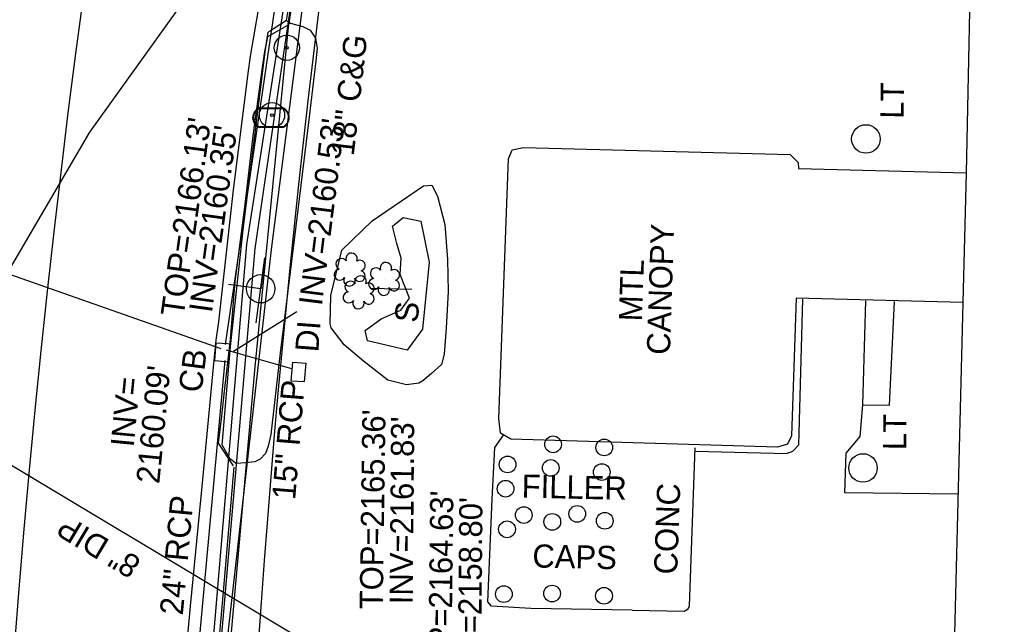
# Model space of a CAD drawing. Extents: x 945964 to 948456, y 631061 to 636061.
# Drawn here: x 946815.5 to 946985.2, y 633029 to 633133.3 of the extents above; entities that cross this region are included whole.
import ezdxf

# ---------------------------------------------------------------- set-up
doc = ezdxf.new("R2010")
doc.units = 0
for name, color, linetype in [('Exist Boundary County Line', 7, 'Continuous'), ('Exist Building', 7, 'Continuous'), ('Exist Building Metal Canopy', 7, 'Continuous'), ('Exist Building Metal Canopy Text', 7, 'Continuous'), ('Exist Horizontal Alignment', 7, 'Continuous'), ('Exist Other Culture Gas Pump or Vent CELL', 7, 'Continuous'), ('Exist Other Culture Gas Pump or Vent Text', 7, 'Continuous'), ('Exist Other Culture Sign CELL', 7, 'Continuous'), ('Exist Other Culture Sign Text', 7, 'Continuous'), ('Exist Right of Way Line', 7, 'Continuous'), ('Exist Roads Change in Surface', 7, 'Continuous'), ('Exist Roads Change in Surface Text', 7, 'Continuous'), ('Exist Roads Curbs', 7, 'Continuous'), ('Exist Roads Curbs Text', 7, 'Continuous'), ('Exist Roads EOP', 7, 'Continuous'), ('Exist Roads EOP Other', 7, 'Continuous'), ('Exist Structure Minor Catch Basin', 7, 'Continuous'), ('Exist Structure Minor Catch Basin Text', 7, 'Continuous'), ('Exist Structure Minor Catch Basin Top Elevation', 7, 'Continuous'), ('Exist Structure Minor Drop Inlet', 7, 'Continuous'), ('Exist Structure Minor Drop Inlet Text', 7, 'Continuous'), ('Exist Structure Minor Drop Inlet Top Elevation', 7, 'Continuous'), ('Exist Structure Minor Pipes RCP 15 Inch', 7, 'Continuous'), ('Exist Structure Minor Pipes RCP 15 Inch Invert', 7, 'Continuous'), ('Exist Structure Minor Pipes RCP 15 Inch Text', 7, 'Continuous'), ('Exist Structure Minor Pipes RCP 18 Inch', 7, 'Continuous'), ('Exist Structure Minor Pipes RCP 18 Inch Invert', 7, 'Continuous'), ('Exist Structure Minor Pipes RCP 24 Inch', 7, 'Continuous'), ('Exist Structure Minor Pipes RCP 24 Inch Invert', 7, 'Continuous'), ('Exist Structure Minor Pipes RCP 24 Inch Text', 7, 'Continuous'), ('Exist Utilities Gas UG Line SUE', 7, 'Continuous'), ('Exist Utilities Other Located Object CELL', 7, 'Continuous'), ('Exist Utilities Other Pole CELL', 7, 'Continuous'), ('Exist Utilities Other Pole With Base Text', 7, 'Continuous'), ('Exist Utilities Power Joint Use Telephone CELL', 7, 'Continuous'), ('Exist Utilities Sanitary Sewer Manhole Text', 7, 'Continuous'), ('Exist Utilities Sanitary Sewer UG Line', 7, 'Continuous'), ('Exist Utilities Sanitary Sewer UG Line Invert Elevation', 7, 'Continuous'), ('Exist Utilities Sanitary Sewer UG Line Text', 7, 'Continuous'), ('Exist Utilities Telephone UG Cable SUE', 7, 'Continuous'), ('Exist Utilities Telephone UG FO SUE', 7, 'Continuous'), ('Exist Utilities Water Meter CELL', 7, 'Continuous'), ('Exist Utilities Water UG Line SUE', 7, 'Continuous'), ('Exist Vegetation Hedge Row', 7, 'Continuous'), ('Exist Vegetation Shrub CELL', 7, 'Continuous')]:
    doc.layers.add(name, color=color, linetype=linetype)

# ---------------------------------------------------------------- blocks, each defined once
blk = doc.blocks.new('EXIST UTILITIES POWER JOINT USE TELEPHONE')
at = {"layer": 'Exist Utilities Power Joint Use Telephone CELL'}
blk.add_line((0, 0), (0, 0), dxfattribs=at)
blk.add_lwpolyline([(-0.1188, 0), (0.108, -0.0008), (0, -0.0004), (0, 0.1125)], dxfattribs=at)
blk.add_circle((0, 0.0001), 0.049, dxfattribs=at)
blk = doc.blocks.new('EXIST UTILITIES OTHER POLE')
at = {"layer": 'Exist Utilities Other Pole CELL'}
blk.add_circle((0, 0), 0.0493, dxfattribs=at)

msp = doc.modelspace()

# ---------------------------------------------------------------- linework, layer by layer
at = {"layer": 'Exist Boundary County Line'}
for p, q in [((947092.82, 633483.47), (946827.48, 633113.91)), ((946827.48, 633113.91), (946750.1, 632981.71))]:
    msp.add_line(p, q, dxfattribs=at)
at = {"layer": 'Exist Building'}
msp.add_lwpolyline([(946978.8, 633106.89), (946978.21, 633084.49), (946976.66, 633022.75), (947059.2, 633020.29), (947060.88, 633083.15), (947040.77, 633083.6), (947042.05, 633115.14), (947051.3, 633115.11), (947050.84, 633101.74), (947104.34, 633099.63), (947106.1, 633132.87), (947031.58, 633135.37), (947033.53, 633169.99), (946989.73, 633171.14), (946989.49, 633154.15), (946979.77, 633154.44)], close=True, dxfattribs=at)
at = {"layer": 'Exist Building Metal Canopy'}
msp.add_lwpolyline([(946978.21, 633084.49), (946949.46, 633085.25), (946948.64, 633061.53), (946947.97, 633060.09), (946946.23, 633059.56), (946900.24, 633060.93), (946898.42, 633061.98), (946898.13, 633064.51), (946899.81, 633109.29), (946900.43, 633110.84), (946902.43, 633111.27), (946948.43, 633110.06), (946949.8, 633108.68), (946949.89, 633107.64), (946978.8, 633106.89), (946978.21, 633084.49)], dxfattribs=at)
at = {"layer": 'Exist Horizontal Alignment'}
msp.add_arc((948718.82, 632879.65), 1909.86, 158.53343, 198.31343, dxfattribs=at)
at = {"layer": 'Exist Other Culture Gas Pump or Vent CELL'}
for centre in [(946907.51, 633060.05), (946916.35, 633059.51), (946899.66, 633056.58), (946907.1, 633055.98), (946915.92, 633055.27), (946899.32, 633052.4), (946911.69, 633048.05), (946902.46, 633047.85), (946907.38, 633046.68), (946916.44, 633046.86), (946899.56, 633045.39), (946899.02, 633034.22), (946907.33, 633034.31), (946916.3, 633033.93)]:
    msp.add_circle(centre, 1.44, dxfattribs=at)
at = {"layer": 'Exist Other Culture Sign CELL'}
msp.add_line((946875.94, 633086.99), (946883.15, 633086.81), dxfattribs=at)
at = {"layer": 'Exist Right of Way Line'}
for radius, start in [(2096.28, 158.90258), (1996.28, 171.75828)]:
    msp.add_arc((948848.33, 632890.69), radius, start, 198.31343, dxfattribs=at)
at = {"layer": 'Exist Roads Change in Surface'}
for points in [[(946861.53, 633133.18), (946864.45, 633150.8), (946867.46, 633167.52)], [(946852.44, 633056.12), (946850.56, 633034.58), (946849.47, 633022.31)]]:
    msp.add_lwpolyline(points, dxfattribs=at)
at = {"layer": 'Exist Roads Curbs'}
for points in [[(946862.18, 633132.7), (946864.33, 633132.12), (946865.59, 633131.5), (946866.48, 633130.12), (946866.78, 633128.4), (946866.54, 633126.22), (946865.41, 633116.53), (946863.13, 633097.7), (946860.4, 633075.85), (946858.79, 633061.73), (946858.36, 633059.71), (946857.87, 633058.48), (946856.94, 633057.49), (946856.01, 633057.06), (946854.35, 633056.87), (946852.87, 633056.76)], [(946861.69, 633132.32), (946858.23, 633130.36), (946857.68, 633127.8), (946857.33, 633125.03), (946855.76, 633113.72), (946854.21, 633100.52), (946852.6, 633088.15), (946851.8, 633078.14), (946850.71, 633068.68), (946850.26, 633064.91), (946849.71, 633060.23), (946852.32, 633056.34)], [(946850.42, 633059.9), (946851.85, 633076.92), (946854, 633097.03), (946856.36, 633116.1), (946857.8, 633127.78), (946858.36, 633131.16)], [(946869.02, 633080.82), (946869.18, 633085.75), (946871.06, 633093.56), (946876.3, 633098.6), (946885.17, 633104.64), (946886.61, 633104.75), (946887.58, 633102.88), (946888.81, 633097.96), (946889.29, 633091.95), (946889.41, 633086.41), (946889.08, 633080.07), (946888.7, 633075.59), (946888.27, 633073.81), (946886.55, 633072.28), (946885.02, 633070.98)], [(946977.38, 633051.45), (946957.86, 633051.66), (946958.07, 633058.54), (946960.54, 633061.41), (946960.99, 633066.87), (946961.5, 633084.79)], [(946850.42, 633059.9), (946851.66, 633057.67)]]:
    msp.add_lwpolyline(points, dxfattribs=at)
at = {"layer": 'Exist Roads EOP'}
msp.add_lwpolyline([(946858.25, 633144.4), (946855.25, 633126.98), (946854.83, 633124), (946852.28, 633103.94), (946849.77, 633081.21), (946849.29, 633078.01), (946848.96, 633074.57), (946846.91, 633052.78), (946844.88, 633032.14), (946843.9, 633021.5), (946843.29, 633011.06), (946842.19, 632997.77), (946841.62, 632984.44), (946841.46, 632979.43), (946840.89, 632976.53), (946840.33, 632952.07), (946839.37, 632921.46), (946838.77, 632883.81), (946838.69, 632880.41), (946838.99, 632838.5)], dxfattribs=at)
at = {"layer": 'Exist Roads EOP Other'}
for points in [[(946861.53, 633133.18), (946858.73, 633131.38)], [(946861.53, 633133.18), (946862.18, 633132.7)], [(946858.73, 633131.38), (946858.36, 633131.16)], [(946932.1, 633058.88), (946947.81, 633058.49), (946948.88, 633058.86), (946949.93, 633059.95), (946950.63, 633085.07)], [(946960.99, 633066.87), (946965.58, 633066.78), (946966.45, 633084.67)], [(946869.21, 633080.12), (946869.02, 633080.82)], [(946885.02, 633070.98), (946884.32, 633070.59), (946882.19, 633070.3), (946879.02, 633071.13), (946874.79, 633074.41), (946871.44, 633077.24), (946869.21, 633080.12)], [(946921.14, 633031.45), (946903.68, 633031.76), (946896.89, 633032.14), (946896.23, 633032.86), (946897.01, 633050.6), (946897.44, 633059.53), (946898.98, 633061.65)], [(946921.14, 633031.45), (946930.13, 633031.27), (946930.84, 633031.65), (946931.08, 633032.18), (946932.05, 633059.45)], [(946851.66, 633057.67), (946852.87, 633056.76)]]:
    msp.add_lwpolyline(points, dxfattribs=at)
at = {"layer": 'Exist Structure Minor Catch Basin'}
msp.add_line((946849.11, 633074.52), (946849.38, 633077.53), dxfattribs=at)
msp.add_lwpolyline([(946849.11, 633074.52), (946850.96, 633074.36), (946851.53, 633074.27), (946851.85, 633077.29), (946851.32, 633077.37), (946849.38, 633077.53)], dxfattribs=at)
at = {"layer": 'Exist Structure Minor Drop Inlet'}
msp.add_line((946862.58, 633074.2), (946864.83, 633074.06), dxfattribs=at)
msp.add_lwpolyline([(946864.83, 633074.06), (946864.57, 633070.81), (946862.31, 633070.95), (946862.58, 633074.2)], dxfattribs=at)
at = {"layer": 'Exist Structure Minor Pipes RCP 15 Inch'}
msp.add_line((946862.44, 633073.06), (946851.16, 633076.3), dxfattribs=at)
at = {"layer": 'Exist Structure Minor Pipes RCP 15 Inch Invert'}
msp.add_lwpolyline([(946852.38, 633076.14), (946863.31, 633082.99)], dxfattribs=at)
at = {"layer": 'Exist Structure Minor Pipes RCP 18 Inch'}
for p, q in [((946850.95, 633077.27), (946867.41, 633188.67)), ((946850.21, 633076.54), (946751.6, 633111.21))]:
    msp.add_line(p, q, dxfattribs=at)
at = {"layer": 'Exist Structure Minor Pipes RCP 24 Inch'}
msp.add_line((946842.17, 632979.3), (946850.94, 633074.53), dxfattribs=at)
at = {"layer": 'Exist Utilities Gas UG Line SUE'}
msp.add_lwpolyline([(946845.5, 632898.11), (946850.73, 633021.39), (946858.89, 633093.64), (946868.46, 633168.18), (946874.18, 633192.21), (946885.66, 633248.38), (946897.01, 633290.1), (946905.35, 633314.3), (946948.47, 633344.78), (946953.35, 633385.57), (946936.81, 633391.16)], dxfattribs=at)
at = {"layer": 'Exist Utilities Other Located Object CELL'}
for centre, radius in [((946861.56, 633128.46), 2.18), ((946861.56, 633128.46), 0.24), ((946859, 633116.83), 2.18), ((946859, 633116.83), 0.24)]:
    msp.add_circle(centre, radius, dxfattribs=at)
at = {"layer": 'Exist Utilities Sanitary Sewer UG Line'}
msp.add_lwpolyline([(946763.27, 633086.81), (946883.13, 633015.07)], dxfattribs=at)
at = {"layer": 'Exist Utilities Telephone UG Cable SUE'}
msp.add_lwpolyline([(946848.57, 632861.08), (946848.15, 632901.79), (946848.19, 632960.21), (946851.51, 633021.85), (946856.12, 633073.43), (946861.87, 633131.99), (946870.69, 633187.61)], dxfattribs=at)
at = {"layer": 'Exist Utilities Telephone UG FO SUE'}
msp.add_lwpolyline([(946843.75, 632861.86), (946845.45, 632875.49), (946846.87, 632959.02), (946849.9, 633021.88), (946856.09, 633093.82), (946867.01, 633168.17), (946873.26, 633207.46), (946887.9, 633278.92), (946901.4, 633327.21), (946927.15, 633399.5), (946955.33, 633464.91), (946976.87, 633502.55), (946990.39, 633526.44), (947042.99, 633595.21), (947065.95, 633626.61), (947283.34, 634211.93), (947296.03, 634240.08), (947307.13, 634250.19), (947335.86, 634268.18), (947320.62, 634317.86), (947311.2, 634351.26), (947308.67, 634385.7), (947324.73, 634436.61)], dxfattribs=at)
at = {"layer": 'Exist Utilities Water Meter CELL'}
msp.add_line((946858.83, 633116.4), (946858.83, 633116.4), dxfattribs=at)
for points in [[(946856.79, 633118.1), (946860.86, 633118.1)], [(946856.79, 633117.96), (946860.86, 633117.96)], [(946860.86, 633114.84), (946856.76, 633114.84)], [(946860.86, 633114.7), (946856.76, 633114.7)]]:
    msp.add_lwpolyline(points, dxfattribs=at)
for centre, radius, start, end in [((946857.52, 633116.39), 1.86, 113.178, 245.9794), ((946857.53, 633116.39), 1.73, 115.3009, 243.7824), ((946860.12, 633116.4), 1.86, 293.6483, 66.3084), ((946860.13, 633116.4), 1.73, 295.1272, 64.8728)]:
    msp.add_arc(centre, radius, start, end, dxfattribs=at)
at = {"layer": 'Exist Utilities Water UG Line SUE'}
msp.add_lwpolyline([(946861.6, 632622.99), (946857.97, 632647.58), (946852.97, 632699.99), (946849.46, 632747.01), (946843.88, 632853.23), (946844.6, 632925.42), (946848.49, 633021.71), (946854.67, 633094.54), (946866.27, 633169.12), (946869.9, 633189.05), (946879.92, 633250.64), (946895.59, 633320.41), (946906.54, 633358.29), (946922.14, 633411.44), (946948.63, 633497.92), (946975.56, 633562.66), (947003.55, 633599.53), (947037.06, 633649.36)], dxfattribs=at)
at = {"layer": 'Exist Vegetation Hedge Row'}
for points in [[(946875.06, 633079.69), (946877.83, 633081.68), (946881.26, 633083.21), (946882.72, 633085.24), (946881.1, 633089.37), (946881.27, 633092.16), (946880.56, 633094.72), (946879.77, 633097.67), (946881.63, 633099.17), (946884.69, 633098.54)], [(946884.69, 633098.54), (946886.12, 633091.46), (946884.95, 633079.92), (946882.35, 633076.27), (946875.48, 633077.89), (946875.06, 633079.69)]]:
    msp.add_lwpolyline(points, dxfattribs=at)
at = {"layer": 'Exist Vegetation Shrub CELL'}
for p, q in [((946872.49, 633090.01), (946872.49, 633090.01)), ((946878.43, 633088.4), (946878.43, 633088.4)), ((946874.05, 633086.09), (946874.05, 633086.09))]:
    msp.add_line(p, q, dxfattribs=at)
for centre, radius, start, end in [((946871, 633091.14), 0.968, 35.8908, 245.4216), ((946872.72, 633092.06), 0.99, 334.8391, 200.4717), ((946874.16, 633090.88), 0.929, 284.4567, 126.0861), ((946870.69, 633089.31), 0.955, 95.1099, 327.9534), ((946876.95, 633089.53), 0.968, 35.8908, 245.4216), ((946878.66, 633090.44), 0.99, 334.8391, 200.4717), ((946880.1, 633089.27), 0.929, 284.4567, 126.0861), ((946872.36, 633088.33), 0.984, 151.2797, 21.387), ((946874.12, 633089.09), 0.937, 204.9913, 73.4601), ((946874.27, 633088.13), 0.99, 334.8391, 200.4717), ((946876.63, 633087.7), 0.955, 95.1099, 327.9534), ((946872.56, 633087.22), 0.968, 35.8908, 245.4216), ((946875.72, 633086.96), 0.929, 284.4567, 126.0861), ((946878.3, 633086.72), 0.984, 151.2797, 21.387), ((946880.07, 633087.47), 0.937, 204.9913, 73.4601), ((946872.24, 633085.39), 0.955, 95.1099, 327.9534), ((946875.68, 633085.16), 0.937, 204.9913, 73.4601), ((946873.92, 633084.41), 0.984, 151.2797, 21.387)]:
    msp.add_arc(centre, radius, start, end, dxfattribs=at)

# ---------------------------------------------------------------- block references
at = {"layer": 'Exist Utilities Other Pole CELL', "xscale": 50, "yscale": 50}
for p in [(946961.5, 633112.72), (946961, 633055.97)]:
    msp.add_blockref('EXIST UTILITIES OTHER POLE', p, dxfattribs=at)
at = {"layer": 'Exist Utilities Power Joint Use Telephone CELL', "xscale": 50, "yscale": 50, "rotation": 82.59528379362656}
msp.add_blockref('EXIST UTILITIES POWER JOINT USE TELEPHONE', (946857.05, 633086.88), dxfattribs=at)

# ---------------------------------------------------------------- texts
at = {"layer": 'Exist Building Metal Canopy Text'}
for s, p in [('CANOPY', (946927.67, 633075.45)), ('MTL', (946922.85, 633081.22))]:
    msp.add_text(s, height=4, rotation=88.1292, dxfattribs=at).set_placement(p)
at = {"layer": 'Exist Other Culture Gas Pump or Vent Text'}
for s, p in [('FILLER', (946902.06, 633050.86)), ('CAPS', (946903.91, 633038.82))]:
    msp.add_text(s, height=4, rotation=358.7677, dxfattribs=at).set_placement(p)
at = {"layer": 'Exist Other Culture Sign Text'}
msp.add_text('S', height=4, rotation=85.7167, dxfattribs=at).set_placement((946884.16, 633080.96))
at = {"layer": 'Exist Roads Change in Surface Text'}
msp.add_text('CONC', height=4, rotation=87.9398, dxfattribs=at).set_placement((946928.92, 633037.55))
at = {"layer": 'Exist Roads Curbs Text'}
msp.add_text('18" C&G', height=4, rotation=83.544, dxfattribs=at).set_placement((946873.1, 633109.69))
at = {"layer": 'Exist Structure Minor Catch Basin Text'}
msp.add_text('CB', height=4, rotation=82.5828, dxfattribs=at).set_placement((946846.82, 633068.84))
at = {"layer": 'Exist Structure Minor Catch Basin Top Elevation'}
msp.add_text("TOP=2166.13'", height=4, rotation=82.0165, dxfattribs=at).set_placement((946843.74, 633081.95))
at = {"layer": 'Exist Structure Minor Drop Inlet Text'}
msp.add_text('DI', height=4, rotation=85.7858, dxfattribs=at).set_placement((946866.99, 633075.87))
at = {"layer": 'Exist Structure Minor Drop Inlet Top Elevation'}
msp.add_text("TOP=2165.36'", height=4, rotation=89.1998, dxfattribs=at).set_placement((946878.12, 633031.57))
at = {"layer": 'Exist Structure Minor Pipes RCP 15 Inch Invert'}
for s, rotation, p in [("INV=2160.53'", 82.8776, (946867.6, 633083.82)), ("INV=2161.83'", 89.5187, (946883.29, 633032.45))]:
    msp.add_text(s, height=4, rotation=rotation, dxfattribs=at).set_placement(p)
at = {"layer": 'Exist Structure Minor Pipes RCP 15 Inch Text'}
msp.add_text('15" RCP', height=4, rotation=85.3013, dxfattribs=at).set_placement((946862.99, 633050.4))
at = {"layer": 'Exist Structure Minor Pipes RCP 18 Inch Invert'}
msp.add_text("INV=2160.35'", height=4, rotation=82.129, dxfattribs=at).set_placement((946848.62, 633082.62))
at = {"layer": 'Exist Structure Minor Pipes RCP 24 Inch Invert'}
for s, p in [("2160.09'", (946839.54, 633053.15)), ('INV=', (946835.12, 633059.47))]:
    msp.add_text(s, height=4, rotation=84.4556, dxfattribs=at).set_placement(p)
at = {"layer": 'Exist Structure Minor Pipes RCP 24 Inch Text'}
msp.add_text('24" RCP', height=4, rotation=84.7374, dxfattribs=at).set_placement((946843.6, 633030.48))
at = {"layer": 'Exist Utilities Other Pole With Base Text'}
for p in [(946968, 633116.2), (946968.45, 633059.03)]:
    msp.add_text('LT', height=4, rotation=89.3158, dxfattribs=at).set_placement(p)
at = {"layer": 'Exist Utilities Sanitary Sewer Manhole Text'}
msp.add_text("TOP=2164.63'", height=4, rotation=89.3731, dxfattribs=at).set_placement((946889.93, 633017.59))
at = {"layer": 'Exist Utilities Sanitary Sewer UG Line Invert Elevation'}
msp.add_text("INV=2158.80'", height=4, rotation=89.5187, dxfattribs=at).set_placement((946895.06, 633018.54))
at = {"layer": 'Exist Utilities Sanitary Sewer UG Line Text'}
msp.add_text('8" DIP', height=4, rotation=149.0995, dxfattribs=at).set_placement((946836.64, 633040.16))

doc.saveas('drawing.dxf')
